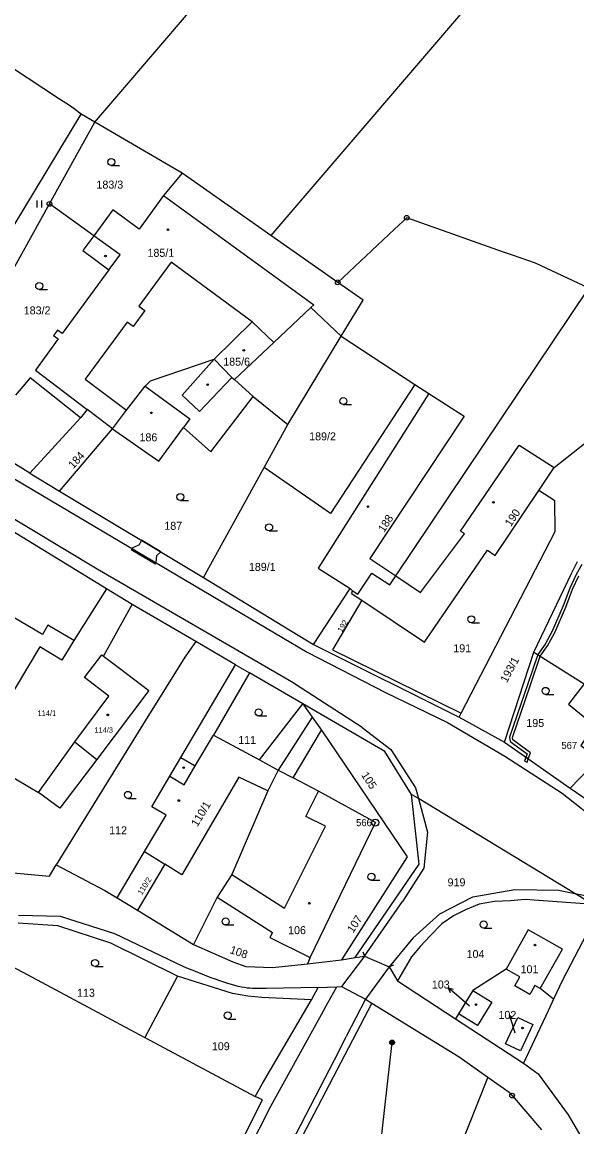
# Model space of a CAD drawing. Extents: x -504988 to -494607, y -1123820 to -1114018.
# Drawn here: x -501686.6 to -501568.7, y -1120941.2 to -1120706.4 of the extents above; entities that cross this region are included whole.
import ezdxf

# ---------------------------------------------------------------- set-up
doc = ezdxf.new("R2010")
doc.units = 0
for name, color, linetype in [('Hranice parcel', 7, 'Continuous'), ('Parcelní čísla', 7, 'Continuous'), ('Pop  PČ popisy', 7, 'Continuous'), ('Poz předměty', 7, 'Continuous'), ('Vnitřní kresba', 7, 'Continuous'), ('Věcná břemena k části', 7, 'Continuous'), ('Značky bodu BP', 7, 'Continuous'), ('Značky budov', 7, 'Continuous'), ('Značky kultur', 7, 'Continuous')]:
    doc.layers.add(name, color=color, linetype=linetype)

msp = doc.modelspace()

# ---------------------------------------------------------------- linework, layer by layer
at = {"layer": 'Hranice parcel'}
for p, q in [((-501680.81, -1120745.07), (-501671.16, -1120727.67)), ((-501671.16, -1120727.67), (-501674.05, -1120725.98)), ((-501652.62, -1120738.53), (-501671.16, -1120727.67)), ((-501633.73, -1120751.77), (-501652.62, -1120738.53)), ((-501699.45, -1120778.69), (-501680.81, -1120745.07)), ((-501671.39, -1120751.86), (-501680.81, -1120745.07)), ((-501619.52, -1120761.74), (-501633.73, -1120751.77)), ((-501630.16, -1120791.97), (-501618.76, -1120773.16)), ((-501618.76, -1120773.16), (-501603.11, -1120783.42)), ((-501637.49, -1120786.02), (-501630.16, -1120791.97)), ((-501672.8, -1120788.77), (-501674.22, -1120790.54)), ((-501684.97, -1120802.3), (-501705.51, -1120789.61)), ((-501674.22, -1120790.54), (-501684.97, -1120802.3)), ((-501678.71, -1120806.09), (-501667.44, -1120792.85)), ((-501635.19, -1120801.11), (-501630.16, -1120791.97)), ((-501684.97, -1120802.3), (-501678.71, -1120806.09)), ((-501648.04, -1120824.47), (-501635.19, -1120801.11)), ((-501678.71, -1120806.09), (-501648.04, -1120824.47)), ((-501668.65, -1120826.84), (-501690.12, -1120813.77)), ((-501648.04, -1120824.47), (-501624.64, -1120838.7)), ((-501624.64, -1120838.7), (-501616.89, -1120826.78)), ((-501616.89, -1120826.78), (-501616.43, -1120827.19)), ((-501668.65, -1120826.84), (-501675.63, -1120837.86)), ((-501663.2, -1120830.22), (-501668.65, -1120826.84)), ((-501669.3, -1120841.18), (-501663.2, -1120830.22)), ((-501649.67, -1120838.09), (-501663.2, -1120830.22)), ((-501641.26, -1120842.99), (-501649.67, -1120838.09)), ((-501624.64, -1120838.7), (-501593.73, -1120854.17)), ((-501584.03, -1120859.43), (-501577.81, -1120840.32)), ((-501641.26, -1120842.99), (-501638.29, -1120844.71)), ((-501626.97, -1120851.3), (-501638.29, -1120844.71)), ((-501626.97, -1120851.3), (-501624.95, -1120854.14)), ((-501624.95, -1120854.14), (-501622.97, -1120856.92)), ((-501593.73, -1120854.17), (-501593.26, -1120853.27)), ((-501593.73, -1120854.17), (-501584.03, -1120859.43)), ((-501584.03, -1120859.43), (-501570.12, -1120869.26)), ((-501696.69, -1120862.21), (-501683.14, -1120870.12)), ((-501570.12, -1120869.26), (-501564.07, -1120863.01)), ((-501666.41, -1120892.53), (-501660.58, -1120882.71)), ((-501660.58, -1120882.71), (-501656.28, -1120885.37)), ((-501656.28, -1120885.37), (-501662.12, -1120895.15)), ((-501666.41, -1120892.53), (-501662.12, -1120895.15)), ((-501645.15, -1120892.4), (-501650.17, -1120902.44)), ((-501662.12, -1120895.15), (-501650.17, -1120902.44)), ((-501625.35, -1120905.23), (-501625.97, -1120906.53)), ((-501625.97, -1120906.53), (-501618.72, -1120905.73)), ((-501618.72, -1120905.73), (-501615.79, -1120905.24)), ((-501615.79, -1120905.24), (-501613.82, -1120904.91)), ((-501613.82, -1120904.91), (-501608.57, -1120907.22)), ((-501608.57, -1120907.22), (-501606.8, -1120910.17)), ((-501653.59, -1120909.15), (-501660.53, -1120922.2)), ((-501606.8, -1120910.17), (-501594.49, -1120918.23)), ((-501590.8, -1120912.24), (-501593.82, -1120917.15)), ((-501593.82, -1120917.15), (-501594.49, -1120918.23)), ((-501594.49, -1120918.23), (-501580.04, -1120927.68)), ((-501660.53, -1120922.2), (-501637.09, -1120934.75)), ((-501587.6, -1120930.64), (-501639.26, -1121059.73))]:
    msp.add_line(p, q, dxfattribs=at)
for points in [[(-501671.16, -1120727.67), (-501570.2, -1120609.84), (-501469.25, -1120492.02), (-501368.29, -1120374.19)], [(-501354.92, -1120426.36), (-501447.86, -1120534.83), (-501540.79, -1120643.3), (-501633.73, -1120751.77)], [(-501674.05, -1120725.98), (-501675.54, -1120724.9), (-501676.53, -1120724.19), (-501678.66, -1120722.79), (-501692.26, -1120713.89)], [(-501711.42, -1120786.44), (-501706.52, -1120779.21), (-501703.28, -1120774.26), (-501674.05, -1120725.98)], [(-501652.62, -1120738.53), (-501656.55, -1120743.32), (-501661.77, -1120750.41), (-501667.32, -1120746.33), (-501671.39, -1120751.86)], [(-501566.15, -1120763.01), (-501577.49, -1120757.7), (-501582.39, -1120755.96), (-501584.28, -1120755.3), (-501604.85, -1120748.03), (-501607.45, -1120750.46), (-501619.52, -1120761.74)], [(-501671.39, -1120751.86), (-501673.69, -1120754.99), (-501668.16, -1120759.09), (-501678.13, -1120772.64), (-501679.13, -1120771.91), (-501679.95, -1120773.04), (-501678.96, -1120773.77), (-501683.81, -1120780.37), (-501672.8, -1120788.77)], [(-501618.76, -1120773.16), (-501614.13, -1120765.51), (-501619.52, -1120761.74)], [(-501616.43, -1120827.19), (-501615.24, -1120827.97), (-501612.25, -1120823.51), (-501608.46, -1120826.05), (-501607.16, -1120824.12), (-501566.15, -1120763.01)], [(-501645.82, -1120778.04), (-501637.7, -1120770.11), (-501633.13, -1120774.53), (-501625.24, -1120767.09), (-501618.76, -1120773.16)], [(-501667.44, -1120792.85), (-501664.41, -1120788.92), (-501660.43, -1120783.78), (-501659.35, -1120782.64), (-501645.82, -1120778.04)], [(-501645.82, -1120778.04), (-501642, -1120781.94), (-501641.5, -1120782.42), (-501637.49, -1120786.02)], [(-501674.22, -1120790.54), (-501684.91, -1120782.06), (-501688, -1120785.74)], [(-501603.11, -1120783.42), (-501621.04, -1120810.88), (-501635.19, -1120801.11)], [(-501603.11, -1120783.42), (-501600.18, -1120785.34), (-501623.65, -1120822.46), (-501616.89, -1120826.78)], [(-501667.44, -1120792.85), (-501657.55, -1120799.74), (-501652.33, -1120792.61), (-501646.47, -1120797.76), (-501637.49, -1120786.02)], [(-501667.44, -1120792.85), (-501670.17, -1120790.77), (-501672.8, -1120788.77)], [(-501576.78, -1120806), (-501573.49, -1120801.1), (-501562.35, -1120792.32)], [(-501614.43, -1120829.28), (-501601.1, -1120838.21), (-501600.66, -1120837.55), (-501587.68, -1120818.66), (-501586.02, -1120819.78), (-501576.78, -1120806)], [(-501593.26, -1120853.27), (-501573.29, -1120814.65), (-501573.37, -1120808.2), (-501576.78, -1120806)], [(-501577.81, -1120840.32), (-501569.81, -1120823.63), (-501568.52, -1120821.08)], [(-501616.43, -1120827.19), (-501616.59, -1120827.84), (-501614.43, -1120829.28)], [(-501614.43, -1120829.28), (-501620.65, -1120839.83), (-501593.26, -1120853.27)], [(-501675.63, -1120837.86), (-501681.13, -1120834.59), (-501682.3, -1120836.57), (-501690.07, -1120831.96), (-501693.34, -1120837.47), (-501695.53, -1120836.17), (-501697.65, -1120839.81), (-501695.49, -1120841.09), (-501705.12, -1120857.31), (-501696.69, -1120862.21)], [(-501675.63, -1120837.86), (-501678.16, -1120842.01), (-501682.83, -1120839.18), (-501696.69, -1120862.21)], [(-501649.67, -1120838.09), (-501652.02, -1120841.42), (-501657.95, -1120850.95), (-501659.57, -1120853.46), (-501679.36, -1120885.55)], [(-501683.14, -1120870.12), (-501675.45, -1120859.35), (-501668.16, -1120849.66), (-501673.35, -1120845.69), (-501669.71, -1120840.87), (-501669.3, -1120841.18)], [(-501577.81, -1120840.32), (-501567.09, -1120847.08), (-501570.48, -1120851.38), (-501564.99, -1120855.86), (-501567.86, -1120860.14), (-501564.07, -1120863.01)], [(-501669.3, -1120841.18), (-501665.93, -1120843.72), (-501659.65, -1120848.45), (-501670.71, -1120863.1), (-501678.62, -1120873.49), (-501683.14, -1120870.12)], [(-501660.58, -1120882.71), (-501656, -1120874.98), (-501659.05, -1120873.17), (-501655.2, -1120866.71), (-501652.85, -1120862.72), (-501641.26, -1120842.99)], [(-501638.29, -1120844.71), (-501645.94, -1120857.94), (-501636.14, -1120863.24), (-501626.97, -1120851.3)], [(-501603.84, -1120870.54), (-501609.52, -1120861.43), (-501626.97, -1120851.3)], [(-501624.95, -1120854.14), (-501632.18, -1120865.38), (-501634.41, -1120869.81), (-501642.06, -1120887.55), (-501645.15, -1120892.4)], [(-501625.35, -1120905.23), (-501611.52, -1120876.55), (-501623.61, -1120869.87), (-501628.97, -1120867.06), (-501622.97, -1120856.92)], [(-501622.97, -1120856.92), (-501604.75, -1120883.81), (-501618.72, -1120905.73)], [(-501615.79, -1120905.24), (-501602.17, -1120885.36), (-501603.84, -1120870.54)], [(-501563.35, -1120895.09), (-501569.13, -1120891.58), (-501602.34, -1120871.45), (-501603.84, -1120870.54)], [(-501570.12, -1120869.26), (-501564.49, -1120873.05), (-501554.43, -1120883.24), (-501554.17, -1120883.55)], [(-501709.57, -1120883.59), (-501701.77, -1120885.98), (-501680.8, -1120887.9), (-501679.36, -1120885.55)], [(-501679.36, -1120885.55), (-501669.05, -1120890.98), (-501666.41, -1120892.53)], [(-501645.15, -1120892.4), (-501633.4, -1120899.88), (-501633.93, -1120900.95), (-501625.35, -1120905.23)], [(-501563.35, -1120895.09), (-501566.03, -1120893.89), (-501579.64, -1120892.88), (-501582.77, -1120893.15), (-501586.2, -1120893.33), (-501589.47, -1120893.87), (-501592.35, -1120895.05), (-501594.93, -1120896.33), (-501597.37, -1120898.08), (-501599.88, -1120900.61), (-501601.9, -1120902.81), (-501603.84, -1120905.07), (-501606.8, -1120910.17)], [(-501563.35, -1120895.09), (-501566.65, -1120900.27), (-501571.7, -1120909.99), (-501573.63, -1120914.05)], [(-501653.59, -1120909.15), (-501667.74, -1120902.15), (-501679, -1120898.49), (-501687.49, -1120897.94)], [(-501573.63, -1120914.05), (-501576.48, -1120911.81), (-501571.75, -1120903.45), (-501579, -1120899.35), (-501583.72, -1120907.68), (-501590.8, -1120912.24)], [(-501650.17, -1120902.44), (-501641.84, -1120906.15), (-501639.06, -1120907.14), (-501633.37, -1120907.33), (-501625.97, -1120906.53)], [(-501690.77, -1120906.04), (-501686.48, -1120908.33), (-501663.72, -1120920.49), (-501660.53, -1120922.2)], [(-501625.11, -1120914.2), (-501635.64, -1120913.68), (-501638.65, -1120913.41), (-501641.86, -1120912.84), (-501653.59, -1120909.15)], [(-501625.11, -1120914.2), (-501623.7, -1120911.6), (-501619.74, -1120911.44), (-501618.7, -1120911.4), (-501613.64, -1120914.09), (-501612.3, -1120914.92)], [(-501590.8, -1120912.24), (-501586.78, -1120914.72), (-501589.8, -1120919.63), (-501593.82, -1120917.15)], [(-501612.3, -1120914.92), (-501635.31, -1120959), (-501656.99, -1121002.02), (-501677.97, -1121034.22)], [(-501637.09, -1120934.75), (-501635.49, -1120932), (-501625.11, -1120914.2)], [(-501612.3, -1120914.92), (-501593.69, -1120926.34), (-501587.6, -1120930.64)], [(-501573.63, -1120914.05), (-501574.8, -1120916.52), (-501580.04, -1120927.68)], [(-501578.04, -1120919.47), (-501580.66, -1120925.03), (-501583.83, -1120923.53), (-501581.21, -1120917.97), (-501578.04, -1120919.47)], [(-501580.04, -1120927.68), (-501576.93, -1120929.96), (-501570.53, -1120938.63), (-501565.92, -1120946.49)], [(-501587.6, -1120930.64), (-501583.06, -1120933.84), (-501582.44, -1120934.56), (-501576.19, -1120941.82)], [(-501808, -1121085.23), (-501806.46, -1121084.9), (-501794.77, -1121081.07), (-501769.15, -1121070.72), (-501753.52, -1121064.4), (-501736.18, -1121057.96), (-501722.95, -1121051.92), (-501704.98, -1121042.13), (-501685.45, -1121024.1), (-501681.37, -1121019.11), (-501666.67, -1120996.11), (-501653.24, -1120970.72), (-501635.55, -1120935.46), (-501637.09, -1120934.75)]]:
    msp.add_lwpolyline(points, dxfattribs=at)
at = {"layer": 'Pop  PČ popisy'}
for p, q in [((-501593.76, -1120913.6), (-501596.03, -1120911.63)), ((-501596.03, -1120911.63), (-501594.94, -1120911.91)), ((-501596.03, -1120911.63), (-501595.6, -1120912.67)), ((-501591.49, -1120915.57), (-501593.76, -1120913.6)), ((-501582.97, -1120917.44), (-501583.09, -1120918.18)), ((-501582.38, -1120919.36), (-501582.97, -1120917.44)), ((-501582.97, -1120917.44), (-501582.45, -1120917.98)), ((-501581.81, -1120921.29), (-501582.38, -1120919.36))]:
    msp.add_line(p, q, dxfattribs=at)
at = {"layer": 'Poz předměty'}
msp.add_line((-501618.47, -1121016.02), (-501607.96, -1120923.26), dxfattribs=at)
for radius in [0.5, 0.4, 0.3, 0.2, 0.1]:
    msp.add_circle((-501607.96, -1120923.26), radius, dxfattribs=at)
at = {"layer": 'Vnitřní kresba'}
for p, q in [((-501656.55, -1120743.32), (-501624.63, -1120766.51)), ((-501665.8, -1120755.89), (-501671.39, -1120751.86)), ((-501668.16, -1120759.09), (-501665.8, -1120755.89)), ((-501654.91, -1120757.43), (-501661.81, -1120766.81)), ((-501637.7, -1120770.11), (-501654.91, -1120757.43)), ((-501660.55, -1120767.74), (-501663.04, -1120771.12)), ((-501661.81, -1120766.81), (-501660.55, -1120767.74)), ((-501624.63, -1120766.51), (-501625.24, -1120767.09)), ((-501664.3, -1120770.19), (-501673.21, -1120782.28)), ((-501663.04, -1120771.12), (-501664.3, -1120770.19)), ((-501633.13, -1120774.53), (-501641.5, -1120782.42)), ((-501730.39, -1120778.62), (-501667.36, -1120815.88)), ((-501652.58, -1120785.74), (-501645.82, -1120778.04)), ((-501642, -1120781.94), (-501648.93, -1120789.22)), ((-501673.21, -1120782.28), (-501664.41, -1120788.92)), ((-501660.43, -1120783.78), (-501650.96, -1120790.74)), ((-501670.64, -1120822.69), (-501733.44, -1120784.94)), ((-501648.93, -1120789.22), (-501652.58, -1120785.74)), ((-501600.18, -1120785.34), (-501592.62, -1120790.18)), ((-501650.96, -1120790.74), (-501652.33, -1120792.61)), ((-501592.62, -1120790.18), (-501612.68, -1120820.43)), ((-501593.39, -1120814.62), (-501580.96, -1120796.34)), ((-501580.96, -1120796.34), (-501573.49, -1120801.1)), ((-501592.57, -1120815.18), (-501593.39, -1120814.62)), ((-501667.36, -1120815.88), (-501626.05, -1120840.34)), ((-501601.89, -1120827.66), (-501592.57, -1120815.18)), ((-501612.68, -1120820.43), (-501607.16, -1120824.12)), ((-501629.35, -1120846.64), (-501670.64, -1120822.69)), ((-501607.16, -1120824.12), (-501601.89, -1120827.66)), ((-501626.05, -1120840.34), (-501609.38, -1120848.93)), ((-501614.33, -1120856.34), (-501629.35, -1120846.64)), ((-501609.38, -1120848.93), (-501596.19, -1120855.26)), ((-501614.33, -1120856.34), (-501608.24, -1120861.03)), ((-501596.19, -1120855.26), (-501584, -1120862.42)), ((-501675.45, -1120859.35), (-501670.71, -1120863.1)), ((-501649.84, -1120864.51), (-501645.94, -1120857.94)), ((-501608.24, -1120861.03), (-501602.95, -1120869.14)), ((-501652.85, -1120862.72), (-501649.84, -1120864.51)), ((-501636.14, -1120863.24), (-501632.18, -1120865.38)), ((-501584, -1120862.42), (-501571.8, -1120870.29)), ((-501655.2, -1120866.71), (-501652.18, -1120868.49)), ((-501652.18, -1120868.49), (-501649.84, -1120864.51)), ((-501632.18, -1120865.38), (-501628.97, -1120867.06)), ((-501640.55, -1120866.92), (-501652.66, -1120887.61)), ((-501634.41, -1120869.81), (-501640.55, -1120866.92)), ((-501626.3, -1120875.25), (-501623.61, -1120869.87)), ((-501602.95, -1120869.14), (-501602.34, -1120871.45)), ((-501571.8, -1120870.29), (-501563.12, -1120877.18)), ((-501602.34, -1120871.45), (-501600.45, -1120878.57)), ((-501622.14, -1120877.33), (-501626.3, -1120875.25)), ((-501630.83, -1120894.74), (-501622.14, -1120877.33)), ((-501600.45, -1120878.57), (-501601.2, -1120886.2)), ((-501652.66, -1120887.61), (-501656.28, -1120885.37)), ((-501642.06, -1120887.55), (-501630.83, -1120894.74)), ((-501601.2, -1120886.2), (-501605.75, -1120893.34)), ((-501597.81, -1120895.93), (-501590.76, -1120892.31)), ((-501590.76, -1120892.31), (-501581.89, -1120890.76)), ((-501581.89, -1120890.76), (-501572.56, -1120890.93)), ((-501572.56, -1120890.93), (-501569.13, -1120891.58)), ((-501569.13, -1120891.58), (-501565.43, -1120892.29)), ((-501613.82, -1120904.91), (-501605.75, -1120893.34)), ((-501678.43, -1120896.5), (-501687.41, -1120896.26)), ((-501666.91, -1120900.15), (-501678.43, -1120896.5)), ((-501603.57, -1120901.07), (-501597.81, -1120895.93)), ((-501652.26, -1120907.2), (-501666.91, -1120900.15)), ((-501603.57, -1120901.07), (-501608.57, -1120907.22)), ((-501614.18, -1120903.98), (-501613.82, -1120904.91)), ((-501613.82, -1120904.91), (-501618.7, -1120911.4)), ((-501608.57, -1120907.22), (-501613.64, -1120914.09)), ((-501607.64, -1120906.86), (-501608.57, -1120907.22)), ((-501580.77, -1120909.35), (-501583.72, -1120907.68)), ((-501581.86, -1120911.26), (-501580.77, -1120909.35)), ((-501578.66, -1120913.07), (-501581.86, -1120911.26)), ((-501577.59, -1120911.18), (-501578.66, -1120913.07)), ((-501576.48, -1120911.81), (-501577.59, -1120911.18)), ((-501623.7, -1120911.6), (-501634.77, -1120911.79)), ((-501622.24, -1120915.97), (-501619.74, -1120911.44)), ((-501622.24, -1120915.97), (-501633.8, -1120936.89)), ((-501613.64, -1120914.09), (-501617.72, -1120922.03)), ((-501619.2, -1120925.02), (-501617.72, -1120922.03)), ((-501636.71, -1120958.75), (-501619.2, -1120925.02)), ((-501633.8, -1120936.89), (-501651.54, -1120971.77))]:
    msp.add_line(p, q, dxfattribs=at)
msp.add_lwpolyline([(-501634.77, -1120911.79), (-501635.23, -1120911.81), (-501635.7, -1120911.82), (-501636.17, -1120911.83), (-501636.65, -1120911.83), (-501637.15, -1120911.82), (-501637.67, -1120911.79), (-501638.21, -1120911.75), (-501638.78, -1120911.69), (-501639.37, -1120911.6), (-501639.99, -1120911.49), (-501640.67, -1120911.34), (-501641.37, -1120911.17), (-501642.12, -1120910.96), (-501642.92, -1120910.72), (-501643.74, -1120910.45), (-501644.6, -1120910.16), (-501645.5, -1120909.84), (-501646.41, -1120909.5), (-501647.35, -1120909.14), (-501648.32, -1120908.77), (-501649.29, -1120908.39), (-501650.27, -1120908), (-501651.27, -1120907.6), (-501652.26, -1120907.2)], dxfattribs=at)
at = {"layer": 'Věcná břemena k části'}
for points in [[(-501657.16, -1120819.01), (-501661.24, -1120816.56), (-501661.77, -1120817.54), (-501663.26, -1120818.24), (-501663.41, -1120818.52), (-501658.3, -1120821.53), (-501658.14, -1120821.26), (-501657.95, -1120819.77)], [(-501579, -1120862.99), (-501579.51, -1120862.63), (-501579.8, -1120863.48), (-501579.25, -1120863.72)]]:
    msp.add_lwpolyline(points, close=True, dxfattribs=at)
msp.add_lwpolyline([(-501567.6, -1120821.67), (-501568.81, -1120823.85), (-501570.18, -1120826.73), (-501571.59, -1120830.51), (-501573.9, -1120835.87), (-501575.42, -1120838.66), (-501576.97, -1120840.85), (-501579.08, -1120847.07), (-501583, -1120858.37), (-501582.86, -1120859.29), (-501579.26, -1120861.91), (-501579.51, -1120862.63), (-501579, -1120862.99), (-501578.55, -1120861.69), (-501582.31, -1120858.96), (-501582.39, -1120858.43), (-501578.52, -1120847.27), (-501576.46, -1120841.17), (-501574.91, -1120838.98), (-501573.36, -1120836.13), (-501571.03, -1120830.73), (-501569.62, -1120826.96), (-501568.28, -1120824.13)], dxfattribs=at)
at = {"layer": 'Značky bodu BP'}
for centre, radius in [((-501680.81, -1120745.07), 0.5), ((-501680.81, -1120745.07), 0.0303), ((-501604.85, -1120748.03), 0.5), ((-501604.85, -1120748.03), 0.0303), ((-501619.52, -1120761.74), 0.5), ((-501619.52, -1120761.74), 0.0303), ((-501611.52, -1120876.55), 0.75), ((-501611.52, -1120876.55), 0.03), ((-501582.44, -1120934.56), 0.5), ((-501582.44, -1120934.56), 0.0303)]:
    msp.add_circle(centre, radius, dxfattribs=at)
at = {"layer": 'Značky budov'}
for centre in [(-501655.6, -1120750.58), (-501668.91, -1120756.16), (-501639.49, -1120776.18), (-501647.17, -1120783.47), (-501659.16, -1120789.47), (-501613.08, -1120809.4), (-501586.41, -1120808.5), (-501668.4, -1120853.65), (-501652.26, -1120864.86), (-501653.3, -1120871.86), (-501625.57, -1120893.67), (-501577.56, -1120902.57), (-501590.11, -1120915.2), (-501580.23, -1120920.19)]:
    msp.add_circle(centre, 0.175, dxfattribs=at)
at = {"layer": 'Značky kultur'}
for p, q in [((-501667.66, -1120736.92), (-501665.91, -1120736.92)), ((-501683.41, -1120745.83), (-501683.41, -1120744.33)), ((-501682.41, -1120745.83), (-501682.41, -1120744.33)), ((-501682.99, -1120763.26), (-501681.24, -1120763.26)), ((-501618.34, -1120787.72), (-501616.59, -1120787.72)), ((-501652.98, -1120808.1), (-501651.23, -1120808.1)), ((-501634.11, -1120814.55), (-501632.36, -1120814.55)), ((-501591.11, -1120834.09), (-501589.36, -1120834.09)), ((-501575.32, -1120849.3), (-501573.57, -1120849.3)), ((-501636.32, -1120853.89), (-501634.57, -1120853.89)), ((-501664.13, -1120871.41), (-501662.38, -1120871.41)), ((-501612.35, -1120888.81), (-501610.6, -1120888.81)), ((-501643.35, -1120898.3), (-501641.6, -1120898.3)), ((-501588.49, -1120898.94), (-501586.74, -1120898.94)), ((-501671.11, -1120907.12), (-501669.36, -1120907.12)), ((-501642.9, -1120918.28), (-501641.15, -1120918.28))]:
    msp.add_line(p, q, dxfattribs=at)
for centre in [(-501667.66, -1120736.17), (-501682.99, -1120762.51), (-501618.34, -1120786.97), (-501652.98, -1120807.35), (-501634.11, -1120813.8), (-501591.11, -1120833.34), (-501575.32, -1120848.55), (-501636.32, -1120853.14), (-501664.13, -1120870.66), (-501612.35, -1120888.06), (-501643.35, -1120897.55), (-501588.49, -1120898.19), (-501671.11, -1120906.37), (-501642.9, -1120917.53)]:
    msp.add_circle(centre, 0.75, dxfattribs=at)

# ---------------------------------------------------------------- texts
at = {"layer": 'Parcelní čísla'}
for s, height, p in [('183/3', 1.7, (-501670.82, -1120741.82)), ('185/1', 1.7, (-501659.97, -1120756.32)), ('183/2', 1.7, (-501686.28, -1120768.55)), ('185/6', 1.7, (-501643.86, -1120779.45)), ('186', 1.7, (-501661.67, -1120795.52)), ('189/2', 1.7, (-501625.59, -1120795.32)), ('187', 1.7, (-501656.39, -1120814.33)), ('189/1', 1.7, (-501638.41, -1120823.06)), ('191', 1.7, (-501594.95, -1120840.35)), ('195', 1.7, (-501579.42, -1120856.23)), ('114/3', 1.139, (-501671.25, -1120857.44)), ('111', 1.7, (-501640.68, -1120859.84)), ('112', 1.7, (-501668.12, -1120879.03)), ('919', 1.7, (-501596.16, -1120890.08)), ('106', 1.7, (-501630.07, -1120900.25)), ('104', 1.7, (-501592.12, -1120905.33)), ('101', 1.7, (-501580.64, -1120908.55)), ('103', 1.7, (-501599.51, -1120911.8)), ('113', 1.7, (-501674.95, -1120913.56)), ('102', 1.7, (-501585.34, -1120918.26)), ('109', 1.7, (-501646.28, -1120924.91))]:
    msp.add_text(s, height=height, dxfattribs=at).set_placement(p)
for s, height, rotation, p in [('184', 1.7, 48, (-501675.73, -1120801.48)), ('190', 1.7, 56, (-501582.72, -1120813.78)), ('188', 1.7, 57, (-501609.67, -1120815)), ('192', 1.2, 59, (-501618.66, -1120836.21)), ('193/1', 1.7, 62, (-501583.56, -1120846.94)), ('114/1', 1.2, 1, (-501683.36, -1120853.92)), ('105', 1.7, 303, (-501614.59, -1120866.44)), ('110/1', 1.7, 59, (-501649.35, -1120877.55)), ('110/2', 1.2, 58, (-501661.17, -1120892.03)), ('107', 1.7, 57, (-501616.26, -1120900.13)), ('108', 1.7, 341, (-501642.6, -1120904.24))]:
    msp.add_text(s, height=height, rotation=rotation, dxfattribs=at).set_placement(p)
at = {"layer": 'Značky bodu BP'}
for s, p in [('567', (-501571.96, -1120860.89)), ('566', (-501615.62, -1120877.3))]:
    msp.add_text(s, height=1.5, dxfattribs=at).set_placement(p)

doc.saveas('drawing.dxf')
